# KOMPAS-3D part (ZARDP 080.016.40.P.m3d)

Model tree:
1. Булева операция:33
2. Булева операция:34
3. Булева операция:35
4. Булева операция:36
5. Булева операция:37
6. Булева операция:38
7. Булева операция:39
8. Булева операция:40
9. Булева операция:41
10. Булева операция:42
11. Булева операция:43
12. Булева операция:44
13. Булева операция:45
14. Булева операция:46
15. Булева операция:47
16. Булева операция:48
17. Булева операция:49
18. Булева операция:50
19. Булева операция:51
20. Булева операция:52
21. Булева операция:53
22. Булева операция:54
23. Булева операция:55
24. Булева операция:56
25. Булева операция:57
26. Булева операция:58
27. Булева операция:59
28. Булева операция:60
29. Булева операция:61
30. Булева операция:62
31. Булева операция:63
32. Булева операция:64
33. Булева операция:65
34. Булева операция:66
35. Булева операция:67

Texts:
  ЗАРДП 080.016.40-ХХ.Р
  ООО "ИК Энерпред-Ярдос"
